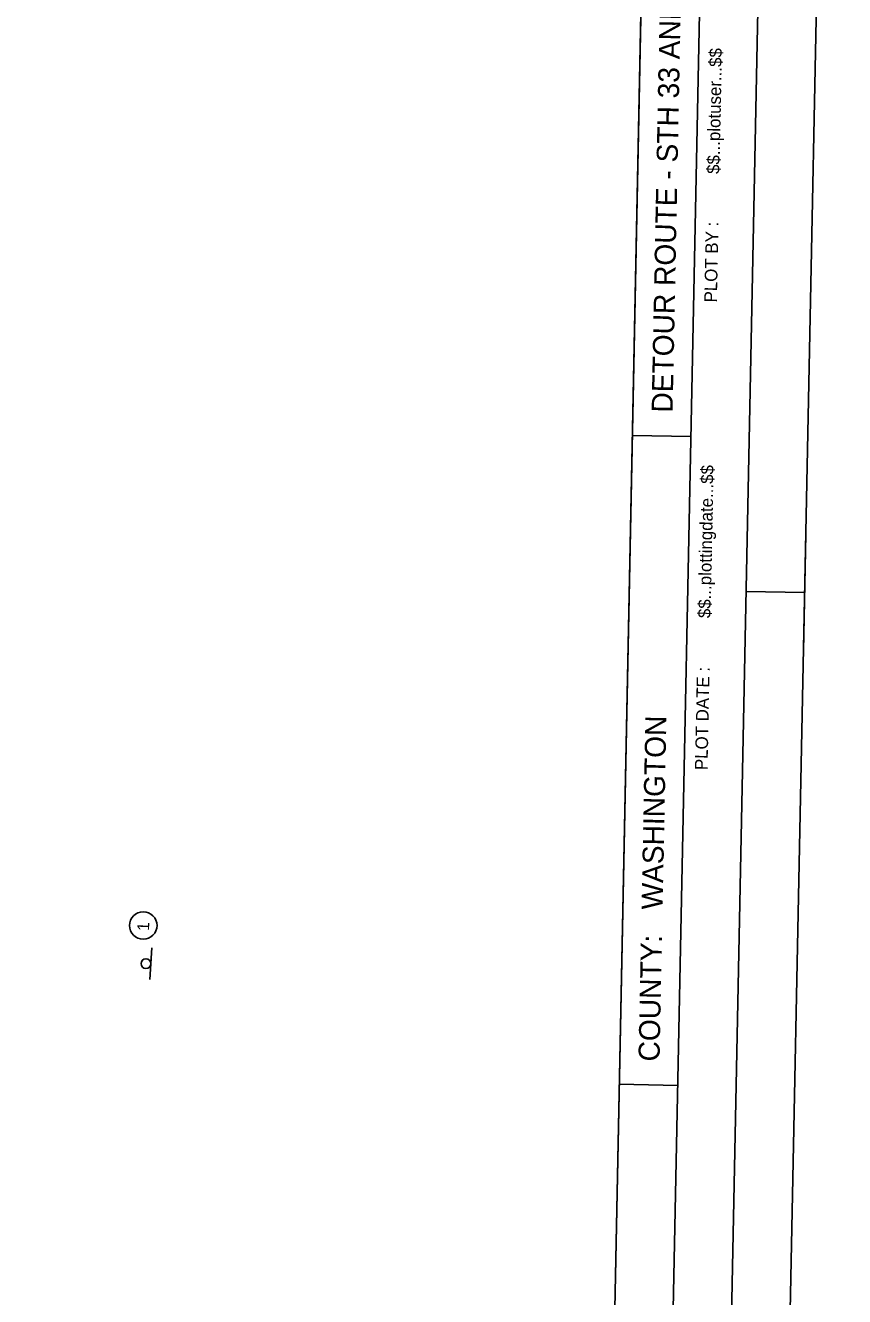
# Model space of a CAD drawing. Extents: x 327762 to 372792, y 127949 to 259367.
# Drawn here: x 364038 to 372792, y 182113 to 195702 of the extents above; entities that cross this region are included whole.
import ezdxf

# ---------------------------------------------------------------- set-up
doc = ezdxf.new("R2010")
doc.units = 0
for name, color, linetype in [('CA-TEXT', 7, 'Continuous'), ('P_MISC_NoPlot', 7, 'Continuous'), ('P_RDWY_Text', 7, 'Continuous'), ('PLT_Sheet_Border', 7, 'Continuous'), ('PLT_Sheet_Info', 7, 'Continuous'), ('SIGNS-POLES', 7, 'Continuous')]:
    doc.layers.add(name, color=color, linetype=linetype)

msp = doc.modelspace()

# ---------------------------------------------------------------- linework, layer by layer
at = {"layer": 'CA-TEXT'}
msp.add_circle((365297, 186080), 147, dxfattribs=at)
at = {"layer": 'P_MISC_NoPlot'}
msp.add_lwpolyline([(345724, 170440), (346294, 198721), (365051, 198328), (365036, 197298), (370642, 197202), (370093, 169949)], close=True, dxfattribs=at)
at = {"layer": 'P_RDWY_Text'}
msp.add_lwpolyline([(344443, 168885), (345298, 211374), (372792, 210820), (371936, 168331)], close=True, dxfattribs=at)
at = {"layer": 'PLT_Sheet_Border'}
for points in [[(371936, 168331), (372792, 210820), (345298, 211374), (344443, 168885)], [(371317, 168643), (372150, 210008), (345907, 210537), (345074, 169172)]]:
    msp.add_lwpolyline(points, close=True, dxfattribs=at)
at = {"layer": 'PLT_Sheet_Info'}
for p, q in [((370093, 169949), (370886, 209315)), ((370718, 169937), (371511, 209302)), ((371149, 191307), (370524, 191319)), ((372353, 189013), (372378, 190263)), ((372365, 189638), (371740, 189651)), ((371009, 184371), (370384, 184383))]:
    msp.add_line(p, q, dxfattribs=at)
at = {"layer": 'SIGNS-POLES'}
for p, q in [((365389, 185841), (365379, 185673)), ((365377, 185672), (365366, 185503))]:
    msp.add_line(p, q, dxfattribs=at)
msp.add_circle((365325, 185673), 52.2, dxfattribs=at)

# ---------------------------------------------------------------- texts
at = {"layer": 'CA-TEXT'}
msp.add_text('1', height=125, rotation=88.8468, dxfattribs=at).set_placement((365359, 186022))
at = {"layer": 'PLT_Sheet_Info'}
for s, height, p in [('DETOUR ROUTE - STH 33 AND CTH D NB OFF RAMP CLOSURES', 224.99, (370954, 191561)), ('$$...plotuser...$$', 134.99, (371455, 194113)), ('PLOT BY :', 135, (371427, 192739)), ('$$...plottingdate...$$', 134.99, (371360, 189365)), ('PLOT DATE :', 134.99, (371327, 187740)), ('WASHINGTON            ', 224.99, (370847, 186249)), ('COUNTY:', 225, (370814, 184625))]:
    msp.add_text(s, height=height, rotation=88.8462, dxfattribs=at).set_placement(p)

doc.saveas('drawing.dxf')
